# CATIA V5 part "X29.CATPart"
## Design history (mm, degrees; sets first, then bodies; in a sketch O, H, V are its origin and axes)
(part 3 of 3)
    line L1 (-413.7, 47.9) -> (-413.7, -49)
    projected curve E1 from Sketch23.S3
    point P3 (-514.2409, 38.4438)
    projected curve E2 from Sketch23.S5
    projected curve E3 from Sketch23.S4
    point P7 (-531.6367, 38.4438)
    projected curve E4 from Sketch23.S6
    spline S1 through (-514.2409, 38.4438) (-510.0811, 43.9813) (-506.2, 47.4)
    spline S2 through (-531.6367, 38.4438) (-522.8264, 42.8606) (-511.4, 46.7)
    spline S3 through (-514.2409, -38.4438) (-510.0811, -43.9813) (-506.2, -47.4)
    spline S4 through (-531.6367, -38.4438) (-522.8264, -42.8606) (-511.4, -46.7)
    point P11 (-514.2409, 38.4438)
    point P12 (-531.6367, 38.4438)
    point P13 (-506.2, 47.4)
    point P14 (-506.2, -47.4)
    point P15 (-514.2409, -38.4438)
    point P16 (-510.0811, 43.9813)
    point P17 (-510.0811, -43.9813)
    point P18 (-511.4, 46.7)
    point P19 (-511.4, -46.7)
    point P20 (-531.6367, -38.4438)
    point P21 (-522.8264, 42.8606)
    point P22 (-522.8264, -42.8606)
    vertical: L1 V
    coincidence: P11 P3, P12 P7
    tangency: S2 E3, S1 E1
    symmetry: S1 S3 H, P13 P14 H, P11 P15 H, P16 P17 H, S2 S4 H, P18 P19 H, P12 P20 H, P21 P22 H
  Project28: ToProject {extract ExtractElem Sketch29.L1}, Support Join33, Direction (0, 0, 1)
  MultiExtract1: ListOfMultiExtractConstraints (MultiExtractConstraint Sketch29.E2; MultiExtractConstraint Sketch29.E1; MultiExtractConstraint Sketch29.S1)
  Project29: ToProject {multiextract ListOfMultiExtractConstraints (MultiExtractConstraint Sketch29.S3; MultiExtractConstraint Sketch29.E2; MultiExtractConstraint Sketch29.E1; MultiExtractConstraint Sketch29.S1)}, Support Join33, Direction (0, 0, 1)
  Plane16: type Offset, RefPlane zx-plane, Offset 582
  Sketch30 on Plane16, origin (0, 582, 0), H (-1, 0, 0), V (0, 0, 1)
    offset curve E1 from edge of Split8
  Project30: ToProject Sketch30, Support Join33, Direction (0, 1, 0)
  Symmetry21: ToTransfor Project30, Reference zx-plane
  Trim1: Trimmed (Project30; Project29)
  Trim2: Trimmed (Trim1; Symmetry21)
  Trim3: Trimmed (Project28; Trim2)
  Split37: ToCut Join33, Cutting Trim3
  Project31: ToProject Sketch30, Support Split37, Direction (0, 1, 0)
  Project32: ToProject {multiextract ListOfMultiExtractConstraints (MultiExtractConstraint Sketch29.S4; MultiExtractConstraint Sketch29.E4; MultiExtractConstraint Sketch29.E3; MultiExtractConstraint Sketch29.S2)}, Support Split37, Direction (0, 0, 1)
  MultiExtract2: ListOfMultiExtractConstraints (MultiExtractConstraint Sketch29.S4; MultiExtractConstraint Sketch29.E3)
  Symmetry22: ToTransfor Project31, Reference zx-plane
  Trim4: Trimmed (Project32; Symmetry22)
  Trim5: Trimmed (Trim4; Project31)
  Split38: ToCut Split37, Cutting Trim5
  Symmetry23: ToTransfor Split31, Reference zx-plane
  Symmetry24: ToTransfor Split33, Reference zx-plane
  Line23: type PtPt, FirstPoint vertex [face of Symmetry23], SecondPoint vertex [face of Symmetry23]
  Line24: type PtPt, FirstPoint vertex [face of Symmetry24], SecondPoint vertex [face of Symmetry24]
  Fill13: Boundary (edge of Symmetry23; edge of Symmetry24; Line24; edge of Symmetry24; edge of Symmetry23; Line23)
  Line25: type PtPt, FirstPoint vertex [face of Symmetry24], SecondPoint vertex [face of Symmetry24]
  Line26: type PtPt, FirstPoint vertex [face of Symmetry23], SecondPoint vertex [face of Symmetry23]
  Line27: type PtPt, FirstPoint vertex [face of Symmetry23], SecondPoint vertex [face of Symmetry23]
  Fill14: Boundary (Line26; edge of Symmetry23; edge of Symmetry24; Line25; edge of Symmetry24; edge of Symmetry24; edge of Symmetry23)
  Fill15: Boundary (edge of Symmetry23; edge of Symmetry24; edge of Symmetry24; edge of Symmetry24; edge of Symmetry23; Line27)
  Symmetry25: ToTransfor Split36, Reference zx-plane
  Line28: type PtPt, FirstPoint vertex [face of Symmetry25], SecondPoint vertex [face of Symmetry25]
  Line29: type PtPt, FirstPoint vertex [face of Symmetry25], SecondPoint vertex [face of Symmetry25]
  Line30: type PtPt, FirstPoint vertex [face of Symmetry25], SecondPoint vertex [face of Symmetry25]
  Fill16: Boundary (Line28; edge of Symmetry25; edge of Symmetry25; edge of Symmetry25)
  Fill17: Boundary (edge of Symmetry25; edge of Symmetry25; edge of Symmetry25; Line29)
  Fill18: Boundary (edge of Symmetry25; edge of Symmetry25; edge of Symmetry25; Line30)
  Intersect10: ToIntersect1 Split36, ToIntersect2 Loft15
  Sketch31 "SIDE DECALS" on Plane16, origin (0, 582, 0), H (-1, 0, 0), V (0, 0, 1)
    line L1 (245.3941, 61.4416) -> (842.6718, 61.4416)
    point P1 (245.3941, 61.4416)
    line L2 (225.3875, 57.4416) -> (842.6718, 57.4416)
    point P2 (225.3875, 57.4416)
    line L3 (183.2063, 49.4416) -> (842.6718, 49.4416)
    point P3 (183.2063, 49.4416)
    line L4 (106.6762, 34.4416) -> (842.6718, 34.4416)
    point P4 (106.6762, 34.4416)
    line L5 (69.9704, 26.4416) -> (842.6718, 26.4416)
    point P5 (69.9704, 26.4416)
    line L6 (53.6718, 22.4416) -> (842.6718, 22.4416)
    point P6 (53.6718, 22.4416)
    projected curve E1 from edge [face of Loft3 | face of Loft3]
    projected curve E2 from edge [face of Loft3 | face of Loft3]
    projected curve E3 from edge [face of Loft3 | face of Loft3]
    projected curve E4 from edge [face of Loft3 | face of Loft3]
    point P10 (313.9943, 75.4416)
    spline S1 through (842.6718, 22.4416) (894.1879, 24.4446) (949.1523, 29.085) (1043.0996, 32.2921) (1122.4, 34.8007) (1204.7, 39.4001) (1232.8006, 41.4948) (1262.2978, 47.8761) (1287.585, 71.5994) (1291.9194, 87.7418) (1293.4, 120.2)
    point P11 (842.6718, 22.4416)
    spline S2 through (842.6718, 26.4416) (894.1879, 28.4446) (949.1523, 33.085) (1043.0996, 36.2921) (1122.4, 38.8007) (1204.7, 43.4001) (1232.8006, 45.4948) (1262.2978, 51.8761) (1285.4, 75.6) (1288.7, 90.4) (1290, 120.2)
    point P12 (842.6718, 26.4416)
    spline S3 through (842.6718, 34.4416) (894.1879, 36.4446) (949.1523, 41.085) (1043.0996, 44.2921) (1122.4, 46.8007) (1204.7, 51.4001) (1232.8006, 53.4948) (1256.3, 59.2) (1277.5, 81) (1282.2, 100.9) (1282.2, 120.2)
    spline S4 through (842.6718, 49.4416) (894.1879, 51.4446) (949.1523, 56.085) (1043.0996, 59.2921) (1122.4, 61.8007) (1204.7, 66.4001) (1232.8006, 68.4948) (1241, 70) (1262.4, 86.3) (1267.4, 108) (1267.5662, 120.2)
    spline S5 through (842.6718, 57.4416) (894.1879, 59.4446) (949.1523, 64.085) (1043.0996, 67.2921) (1122.4, 69.8007) (1204.5, 74.4) (1232.8006, 76.4948) (1242.7, 79.2) (1257.2, 93) (1259.2, 107.6) (1258.5, 120.2)
    spline S6 through (842.6718, 61.4416) (894.1879, 63.4446) (949.1523, 68.085) (1043.0996, 71.2921) (1122.4, 73.8007) (1204.7, 78.4001) (1232.8006, 80.4948) (1247.2, 85.8) (1254, 94.4) (1255.9, 108.2) (1254.9, 120.2)
    point P13 (842.6718, 34.4416)
    construction line L7 (842.6718, 22.4416) -> (842.6718, 26.4416)
    construction line L8 (842.6718, 26.4416) -> (842.6718, 34.4416)
    construction line L9 (842.6718, 34.4416) -> (842.6718, 49.4416)
    point P14 (842.6718, 49.4416)
    construction line L10 (842.6718, 49.4416) -> (842.6718, 57.4416)
    point P15 (842.6718, 49.4416)
    point P16 (842.6718, 57.4416)
    construction line L11 (842.6718, 57.4416) -> (842.6718, 61.4416)
    point P17 (842.6718, 61.4416)
    line L12 (1293.4, 120.2) -> (1290, 120.2)
    point P18 (1293.4, 120.2)
    point P19 (1290, 120.2)
    line L13 (1290, 120.2) -> (1282.2, 120.2)
    point P20 (1282.2, 120.2)
    line L14 (1282.2, 120.2) -> (1267.5662, 120.2)
    point P21 (1267.5662, 120.2)
    line L15 (1267.5662, 120.2) -> (1258.5, 120.2)
    point P22 (1258.5, 120.2)
    line L16 (1258.5, 120.2) -> (1254.9, 120.2)
    point P23 (1254.9, 120.2)
    point P24 (842.6718, 57.4416)
    point P25 (842.6718, 61.4416)
    frozenspline C1
    point P26 (842.6718, 22.4416)
    point P27 (1293.4, 120.2)
    point P28 (842.6718, 26.4416)
    point P29 (842.6718, 34.4416)
    point P30 (842.6718, 49.4416)
    point P31 (842.6718, 57.4416)
    point P32 (842.6718, 61.4416)
    point P33 (1290, 120.2)
    point P34 (1282.2, 120.2)
    point P35 (1267.5662, 120.2)
    point P36 (1258.5, 120.2)
    point P37 (1254.9, 120.2)
    distance L1 L2 = 4
    distance L3 L2 = 8
    distance L5 L4 = 8 {= Sketch31.distance(L3 L2)}
    distance L5 L6 = 4 {= Sketch31.distance(L1 L2)}
    distance L3 L4 = 15
    distance P10 L1 = 14
    length L6 = 789
    horizontal: L1 H, L2 H, L3 H, L5 H, L4 H, L6 H, L12 H, L13 H, L14 H, L15 H, L16 H
    coincidence: P1 E1, P2 E1, P3 E1, P4 E1, P5 E1, P6 E1, P26 L6, P26 P11, P28 P12, P29 P13, P30 P14, P30 P15, P31 P16, P32 P17, P27 P18, P33 P19, P34 P20, P35 P21, P36 P22, P37 P23, P31 P24, P32 P25
    tangency: S1 L6
    fix: P27
    vertical: L7 V, L8 V, L9 V, L10 V, L11 V
  Project33: ToProject {multiextract ListOfMultiExtractConstraints (MultiExtractConstraint Sketch31.E4; MultiExtractConstraint Sketch31.L1; MultiExtractConstraint Sketch31.L2)}, Support Split8, Direction (0, 1, 0)
  Project34: ToProject {multiextract ListOfMultiExtractConstraints (MultiExtractConstraint Sketch31.L3; MultiExtractConstraint Sketch31.E4; MultiExtractConstraint Sketch31.L4)}, Support Split8, Direction (0, 1, 0)
  MultiExtract3: ListOfMultiExtractConstraints (MultiExtractConstraint Sketch31.L3; MultiExtractConstraint Sketch31.E4; MultiExtractConstraint Sketch31.L4; MultiExtractConstraint Sketch31.L5; MultiExtractConstraint Sketch31.E4; MultiExtractConstraint Sketch31.L6)
  Project35: ToProject {multiextract ListOfMultiExtractConstraints (MultiExtractConstraint Sketch31.L5; MultiExtractConstraint Sketch31.E4; MultiExtractConstraint Sketch31.L6)}, Support Split8, Direction (0, 1, 0)
  Split39: ToCut Split8, Cutting Project35
  MultiSel10
  Sketch32 on Plane15, origin (0, 0, 582), H (1, 0, 0), V (0, 1, 0)
    projected curve E1 from edge of MultiSel10
    projected curve E2 from edge of Project33
    point P4 (-245.3941, 0.8143)
    projected curve E3 from edge of Project33
    point P5 (-225.3875, 1.4233)
    projected curve E4 from edge of MultiSel10
    projected curve E5 from edge of Project34
    point P10 (-183.2063, 3.0832)
    projected curve E6 from edge of MultiSel10
    projected curve E7 from edge of Project34
    point P13 (-106.6762, 2.6765)
    projected curve E8 from edge of MultiSel10
    line L1 (-245.3941, 0.8143) -> (-245.3654, 0)
    point P17 (-245.3654, 0)
    line L2 (-225.3875, 1.4233) -> (-225.3125, 0)
    point P18 (-225.3125, 0)
    line L3 (-183.2063, 3.0832) -> (-182.9985, 0)
    point P19 (-182.9985, 0)
    line L4 (-106.6762, 2.6765) -> (-106.5764, 0)
    point P20 (-106.5764, 0)
    point P21 (-106.5764, 0)
    point P22 (-106.6762, -2.6765)
    line L5 (-106.6762, -2.6765) -> (-106.5764, 0)
    point P23 (-182.9985, 0)
    point P24 (-183.2063, -3.0832)
    line L6 (-183.2063, -3.0832) -> (-182.9985, 0)
    point P25 (-225.3125, 0)
    point P26 (-225.3875, -1.4233)
    line L7 (-225.3875, -1.4233) -> (-225.3125, 0)
    point P27 (-245.3654, 0)
    point P28 (-245.3941, -0.8143)
    line L8 (-245.3941, -0.8143) -> (-245.3654, 0)
    coincidence: P17 H, P18 H, P19 H, P20 H
    tangency: L4 E7, L3 E5, L2 E3, L1 E2
    symmetry: P20 P21 H, P13 P22 H, L4 L5 H, P19 P23 H, P10 P24 H, L3 L6 H, P18 P25 H, P5 P26 H, L2 L7 H, P17 P27 H, P4 P28 H, L1 L8 H
  Project36: ToProject {multiextract ListOfMultiExtractConstraints (MultiExtractConstraint Sketch32.L1; MultiExtractConstraint Sketch32.L8; MultiExtractConstraint Sketch32.L2; MultiExtractConstraint Sketch32.L7; MultiExtractConstraint Sketch32.L3; MultiExtractConstraint Sketch32.L6; MultiExtractConstraint Sketch32.L4; MultiExtractConstraint Sketch32.L5)}, Support Split39, Direction (0, 0, 1)
  Join34: Elements {multiextract ListOfMultiExtractConstraints (MultiExtractConstraint edge of Project33; MultiExtractConstraint edge of Project36; MultiExtractConstraint edge of Project36; MultiExtractConstraint edge of MultiSel10)}
  Project37: ToProject {multiextract ListOfMultiExtractConstraints (MultiExtractConstraint Sketch32.L2; MultiExtractConstraint Sketch32.L7)}, Support Split39, Direction (0, 0, 1)
  Project38: ToProject {multiextract ListOfMultiExtractConstraints (MultiExtractConstraint Sketch32.L3; MultiExtractConstraint Sketch32.L6)}, Support Split39, Direction (0, 0, 1)
  Project39: ToProject {multiextract ListOfMultiExtractConstraints (MultiExtractConstraint Sketch32.L4; MultiExtractConstraint Sketch32.L5)}, Support Split39, Direction (0, 0, 1)
  Join35: Elements {multiextract ListOfMultiExtractConstraints (MultiExtractConstraint edge of Project33; MultiExtractConstraint edge of Project37; MultiExtractConstraint edge of Project37; MultiExtractConstraint edge of MultiSel10)}
  Join36: Elements {multiextract ListOfMultiExtractConstraints (MultiExtractConstraint edge of Project34; MultiExtractConstraint edge of Project38; MultiExtractConstraint edge of Project38; MultiExtractConstraint edge of MultiSel10)}
  Join37: Elements {multiextract ListOfMultiExtractConstraints (MultiExtractConstraint edge of Project34; MultiExtractConstraint edge of Project39; MultiExtractConstraint edge of Project39; MultiExtractConstraint edge of MultiSel10)}
  Split40: ToCut Split39, Cutting Join37
  Split41: ToCut Split40, Cutting Join36
  Split42: ToCut {split ToCut Split40, Cutting Join36}, Cutting Join35
  Split43: ToCut {split ToCut {split ToCut Split40, Cutting Join36}, Cutting Join35}, Cutting Join34
  Project40: ToProject {multiextract ListOfMultiExtractConstraints (MultiExtractConstraint Sketch31.L1; MultiExtractConstraint Sketch31.L2; MultiExtractConstraint Sketch31.S6; MultiExtractConstraint Sketch31.S5; MultiExtractConstraint Sketch31.L16)}, Support {multiextract ListOfMultiExtractConstraints (MultiExtractConstraint face of Loft15; MultiExtractConstraint face of Loft16)}, Direction (0, 1, 0)
  Project41: ToProject {multiextract ListOfMultiExtractConstraints (MultiExtractConstraint Sketch31.L3; MultiExtractConstraint Sketch31.L4; MultiExtractConstraint Sketch31.S4; MultiExtractConstraint Sketch31.S3; MultiExtractConstraint Sketch31.L14)}, Support {multiextract ListOfMultiExtractConstraints (MultiExtractConstraint face of Loft15; MultiExtractConstraint face of Loft16)}, Direction (0, 1, 0)
  Project42: ToProject {multiextract ListOfMultiExtractConstraints (MultiExtractConstraint Sketch31.L5; MultiExtractConstraint Sketch31.S2; MultiExtractConstraint Sketch31.L12; MultiExtractConstraint Sketch31.S1; MultiExtractConstraint Sketch31.L6)}, Support {multiextract ListOfMultiExtractConstraints (MultiExtractConstraint face of Loft15; MultiExtractConstraint face of Loft16)}, Direction (0, 1, 0)
  Split44: ToCut Loft15, Cutting {multiextract ListOfMultiExtractConstraints (MultiExtractConstraint edge of Project40; MultiExtractConstraint edge of Project40)}
  Split45: ToCut {split ToCut Loft15, Cutting {multiextract ListOfMultiExtractConstraints (MultiExtractConstraint edge of Project40; MultiExtractConstraint edge of Project40)}}, Cutting {multiextract ListOfMultiExtractConstraints (MultiExtractConstraint edge of Project40; MultiExtractConstraint edge of Project40)}
  Split46: ToCut Split45, Cutting {multiextract ListOfMultiExtractConstraints (MultiExtractConstraint edge of Project41; MultiExtractConstraint edge of Project41)}
  Split47: ToCut Split46, Cutting {multiextract ListOfMultiExtractConstraints (MultiExtractConstraint edge of Project41; MultiExtractConstraint edge of Project41)}
  Split48: ToCut {extract ExtractElem face of Loft15}, Cutting {multiextract ListOfMultiExtractConstraints (MultiExtractConstraint edge of Project42; MultiExtractConstraint edge of Project42)}
  Split49: ToCut Split47, Cutting {multiextract ListOfMultiExtractConstraints (MultiExtractConstraint edge of Project42; MultiExtractConstraint edge of Project42)}
  Split50: ToCut Split49, Cutting {multiextract ListOfMultiExtractConstraints (MultiExtractConstraint edge of Project42; MultiExtractConstraint edge of Project42)}
  Split51: ToCut Loft16, Cutting Project40
  Split52: ToCut Split51, Cutting {extract ExtractElem edge of Project41}
  Split53: ToCut Split52, Cutting Project42
  Split54: ToCut {split ToCut {extract ExtractElem face of Loft15}, Cutting {multiextract ListOfMultiExtractConstraints (MultiExtractConstraint edge of Project42; MultiExtractConstraint edge of Project42)}}, Cutting {multiextract ListOfMultiExtractConstraints (MultiExtractConstraint edge of Project41; MultiExtractConstraint edge of Project41)}
  MultiSel11
  MultiSel12
  Symmetry26: ToTransfor Split44, Reference zx-plane
  Symmetry27: ToTransfor {split ToCut {split ToCut {extract ExtractElem face of Loft15}, Cutting {multiextract}}, Cutting {multiextract ListOfMultiExtractConstraints (MultiExtractConstraint edge of Project41; MultiExtractConstraint edge of Project41)}}, Reference zx-plane
  Symmetry28: ToTransfor {split ToCut Split49, Cutting {multiextract ListOfMultiExtractConstraints (MultiExtractConstraint edge of Project42; MultiExtractConstraint edge of Project42)}}, Reference zx-plane
  MultiSel13
  Project43: ToProject {multiextract ListOfMultiExtractConstraints (MultiExtractConstraint Sketch27.C5; MultiExtractConstraint Sketch27.L25; MultiExtractConstraint Sketch27.C4; MultiExtractConstraint Sketch27.E6)}, Support {multiextract ListOfMultiExtractConstraints (MultiExtractConstraint face of Loft7; MultiExtractConstraint face of Loft8; MultiExtractConstraint face of Loft24)}, Direction (0, 0, 1)
  Project44: ToProject {multiextract ListOfMultiExtractConstraints (MultiExtractConstraint Sketch27.C5; MultiExtractConstraint Sketch27.C4; MultiExtractConstraint Sketch27.E6)}, Support Loft8, Direction (0, 0, 1)
  MultiExtract4: ListOfMultiExtractConstraints (MultiExtractConstraint Sketch27.C5; MultiExtractConstraint Sketch27.C4)
  Project45: ToProject {multiextract ListOfMultiExtractConstraints (MultiExtractConstraint Sketch27.C5; MultiExtractConstraint Sketch27.C4; MultiExtractConstraint Sketch27.L25)}, Support Loft7, Direction (0, 0, 1)
  Split55: ToCut Loft7, Cutting Project45
  Split56: ToCut Loft8, Cutting Project44
  Split57: ToCut Loft24, Cutting Project43
  Project46: ToProject {multiextract ListOfMultiExtractConstraints (MultiExtractConstraint Sketch27.C3; MultiExtractConstraint Sketch27.L24; MultiExtractConstraint Sketch27.C2; MultiExtractConstraint Sketch27.C1; MultiExtractConstraint Sketch27.L7; MultiExtractConstraint Sketch27.S1)}, Support Split55, Direction (0, 0, 1)
  Project47: ToProject {multiextract ListOfMultiExtractConstraints (MultiExtractConstraint Sketch27.C3; MultiExtractConstraint Sketch27.C2; MultiExtractConstraint Sketch27.L24)}, Support Split55, Direction (0, 0, 1)
  MultiExtract5: ListOfMultiExtractConstraints (MultiExtractConstraint Sketch27.C3; MultiExtractConstraint Sketch27.L24; MultiExtractConstraint Sketch27.C2)
  Project48: ToProject {multiextract ListOfMultiExtractConstraints (MultiExtractConstraint Sketch27.C3; MultiExtractConstraint Sketch27.C2; MultiExtractConstraint Sketch27.E6; MultiExtractConstraint Sketch27.C1; MultiExtractConstraint Sketch27.L6; MultiExtractConstraint Sketch27.S1)}, Support Split56, Direction (0, 0, 1)
  Project49: ToProject {multiextract ListOfMultiExtractConstraints (MultiExtractConstraint Sketch27.C3; MultiExtractConstraint Sketch27.C2; MultiExtractConstraint Sketch27.E6; MultiExtractConstraint Sketch27.C1; MultiExtractConstraint Sketch27.L6; MultiExtractConstraint Sketch27.S1)}, Support Split57, Direction (0, 0, 1)
  Split58: ToCut Split55, Cutting Project47
  Split59: ToCut Split58, Cutting Project46
  Split60: ToCut Split56, Cutting Project48
  Split61: ToCut Split57, Cutting Project49
  MultiSel14
  Project50: ToProject Sketch25, Support Loft2, Direction (0, 0, 1)
  Split62: ToCut Loft2, Cutting Project50
  MultiSel15
  Sketch33 on Plane3, origin (0, 291, 0), H (-1, 0, 0), V (0, 0, 1)
    line L1 (1317.5236, 250.1) -> (1318.922, 238.2687)
    point P1 (1317.5236, 250.1)
    point P2 (1322.8423, 205.1)
    line L2 (1311.4819, 250.1) -> (1313.7079, 231.2665)
    point P3 (1311.4819, 250.1)
    point P4 (1316.8005, 205.1)
    construction line L3 (1285.1219, 205.1) -> (1421.9219, 205.1)
    point P5 (1285.1219, 205.1)
    construction line L4 (1283.1552, 250.1) -> (1402.7552, 250.1)
    line L5 (1294.2231, 205.1) -> (1313.7079, 231.2665)
    point P9 (1294.2231, 205.1)
    point P10 (1327.7322, 250.1)
    line L6 (1297.9635, 205.1) -> (1314.2202, 226.9315)
    point P11 (1297.9635, 205.1)
    point P12 (1331.4726, 250.1)
    line L7 (1354.67, 211.1) -> (1352.4359, 205.1)
    point P13 (1352.4359, 205.1)
    point P14 (1354.67, 211.1)
    line L8 (1378.3269, 205.1) -> (1380.561, 211.1)
    point P15 (1378.3269, 205.1)
    line L9 (1380.561, 211.1) -> (1362.4419, 211.1)
    line L10 (1362.4419, 211.1) -> (1384.3566, 237.7168)
    line L11 (1354.67, 211.1) -> (1376.5846, 237.7168)
    point P19 (1376.5846, 237.7168)
    line L12 (1327.5005, 227.1) -> (1328.9899, 231.1)
    line L13 (1328.9899, 231.1) -> (1344.9899, 231.1)
    line L14 (1344.9899, 231.1) -> (1343.5005, 227.1)
    line L15 (1343.5005, 227.1) -> (1327.5005, 227.1)
    reference projected line E1 (1375.2, 318.7844) -> (1434.7, 318.7844) from edge of Loft19
    construction line L16 (1376.5846, 237.7168) -> (1384.3566, 237.7168)
    line L17 (1384.3566, 237.7168) -> (1386.7541, 244.1559)
    line L18 (1386.7541, 244.1559) -> (1379.5345, 250.1)
    line L19 (1379.5345, 250.1) -> (1360.5503, 250.1)
    line L20 (1360.5503, 250.1) -> (1356.5638, 244.7464)
    line L21 (1356.5638, 244.7464) -> (1354.8338, 240.1)
    line L22 (1354.8338, 240.1) -> (1359.645, 240.1)
    line L23 (1359.645, 240.1) -> (1361.4323, 244.9)
    point P30 (1361.4323, 244.9)
    line L24 (1361.4323, 244.9) -> (1378.0783, 244.9)
    point P31 (1361.4323, 244.9)
    line L25 (1378.0783, 244.9) -> (1378.9821, 244.1559)
    line L26 (1378.9821, 244.1559) -> (1376.5846, 237.7168)
    construction line L27 (1378.9821, 244.1559) -> (1386.7541, 244.1559)
    line L28 (1409.5004, 211.1) -> (1419.4109, 237.7168)
    point P34 (1409.5004, 211.1)
    point P35 (1419.4109, 237.7168)
    line L29 (1409.5004, 211.1) -> (1404.5604, 205.1)
    point P36 (1404.5604, 205.1)
    line L30 (1404.5604, 205.1) -> (1389.5088, 205.1)
    line L31 (1389.5088, 205.1) -> (1387.1314, 211.1)
    point P38 (1387.1314, 211.1)
    line L32 (1387.1314, 211.1) -> (1391.4665, 211.1)
    point P39 (1391.4665, 211.1)
    line L33 (1391.4665, 211.1) -> (1392.5803, 208.289)
    point P40 (1391.4665, 211.1)
    line L34 (1392.5803, 208.289) -> (1400.7836, 208.289)
    line L35 (1400.7836, 208.289) -> (1403.098, 211.1)
    point P43 (1403.098, 211.1)
    line L36 (1403.098, 211.1) -> (1409.4061, 228.0419)
    point P44 (1413.0085, 237.7168)
    construction line L37 (1413.0085, 237.7168) -> (1419.4109, 237.7168)
    line L38 (1398.7382, 244.9) -> (1395.3584, 235.8226)
    point P45 (1398.7382, 244.9)
    construction line L39 (1398.7382, 244.9) -> (1393.8845, 244.9)
    point P47 (1398.7382, 244.9)
    line L40 (1393.8845, 244.9) -> (1390.5046, 235.8226)
    construction line L41 (1390.5046, 235.8226) -> (1395.3584, 235.8226)
    construction line L42 (1354.8338, 240.1) -> (1352.4359, 205.1)
    line L43 (1393.8845, 244.9) -> (1398.1658, 250.1)
    point P50 (1398.1658, 250.1)
    line L44 (1398.1658, 250.1) -> (1412.3421, 250.1)
    line L45 (1412.3421, 250.1) -> (1419.2128, 244.3629)
    line L46 (1419.2128, 244.3629) -> (1419.4109, 237.7168)
    point P53 (1419.4109, 237.7168)
    line L47 (1398.7382, 244.9) -> (1399.2007, 245.4616)
    line L48 (1399.2007, 245.4616) -> (1412.1217, 245.4616)
    line L49 (1412.1217, 245.4616) -> (1412.7943, 244.9)
    point P56 (1412.7943, 244.9)
    line L50 (1412.7943, 244.9) -> (1413.0085, 237.7168)
    line L51 (1395.3584, 235.8226) -> (1396.7358, 231.9)
    line L52 (1390.5046, 235.8226) -> (1393.3569, 227.7)
    line L53 (1396.7358, 231.9) -> (1408.5572, 231.9)
    line L54 (1408.5572, 231.9) -> (1411.1864, 232.8233)
    point P60 (1411.1864, 232.8233)
    line L55 (1393.3569, 227.7) -> (1408.4325, 227.7)
    line L56 (1408.4325, 227.7) -> (1409.4061, 228.0419)
    line L57 (1411.1864, 232.8233) -> (1413.0085, 237.7168)
    line L58 (1318.922, 238.2687) -> (1327.7322, 250.1)
    line L59 (1314.2202, 226.9315) -> (1316.8005, 205.1)
    line L60 (1319.4344, 233.9337) -> (1331.4726, 250.1)
    point P66 (1319.4344, 233.9337)
    line L61 (1319.4344, 233.9337) -> (1322.8423, 205.1)
    line L62 (1311.4819, 250.1) -> (1317.5236, 250.1)
    line L63 (1327.7322, 250.1) -> (1331.4726, 250.1)
    line L64 (1294.2231, 205.1) -> (1297.9635, 205.1)
    line L65 (1316.8005, 205.1) -> (1322.8423, 205.1)
    line L66 (1352.4359, 205.1) -> (1378.3269, 205.1)
    distance L4 L3 = 45
    distance P14 L3 = 6
    distance L9 L3 = 6 {= Sketch33.distance(P14 L3)}
    distance L2 L1 = 6
    distance L11 L10 = 6 {= Sketch33.distance(L2 L1)}
    distance L5 L6 = 3
    distance L13 L15 = 4
    length L13 = 16
    distance L4 E1 = 68.6844
    angle L7 L3 = 110.4223
    distance P13 P5 = 67.3141
    length L3 = 136.8
    distance L36 L28 = 6
    distance L16 L3 = 32.6168
    distance L22 L3 = 35
    horizontal: L3 H, L4 H, L9 H, L13 H, L15 H, L16 H, L19 H, L22 H, L24 H, L27 H, L30 H, L32 H, L34 H, L37 H, L39 H, L41 H, L44 H, L48 H, L53 H, L55 H, L62 H, L63 H, L64 H, L65 H, L66 H
    coincidence: P1 L4, P3 L4, P4 L3, P2 L3, P9 L3, P10 L4, P11 L3, P12 L4, P13 L3, P15 L3, P31 L23, P30 P31, P34 L9, P35 L16, P36 L3, P38 L9, L31 P19, P40 L32, P43 L32, P44 L16, P45 L24, P47 L38, P47 L24, P50 L4, L19 L4, P53 L28, L46 P35, P40 P39, P56 L24, P60 L36, L36 L57, L5 L58, L2 L59, L1 P66, L6 L60, L1 L61
    parallelism: L8 L7, L12 L7, L14 L7, L14 L12, L17 L8, L20 L6, L21 L14, L23 L7, L25 L18, L26 L17, L28 L8, L29 L10, L33 L31, L35 L29, L38 L8, L40 L38, L43 L10, L47 L43, L49 L45, L50 L46, L52 L51, L56 L54
    perpendicularity: L18 L11, L54 L51
  Project51: ToProject Sketch33, Support Loft19, Direction (0, 1, 0)
  Split63: ToCut Loft19, Cutting {extract ExtractElem edge of Project51}
  Split64: ToCut Split63, Cutting {extract ExtractElem edge of Project51}
  Split65: ToCut Split64, Cutting {extract ExtractElem edge of Project51}
  Split66: ToCut Split65, Cutting {extract ExtractElem edge of Project51}
  Split67: ToCut Split66, Cutting {extract ExtractElem edge of Project51}
Body1 (main body)
Relations
  Sketch26.Value = Sketch26.Value +3.5mm
  Sketch26.Value = Sketch26.Value +11mm
  Sketch26.Value = Sketch26.Value +Sketch26.Value
  Sketch27.Value = Sketch27.Value +3.5mm
  Sketch27.Value = Sketch27.Value +Sketch27.Value
  Sketch27.Value = Sketch27.Value +11mm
